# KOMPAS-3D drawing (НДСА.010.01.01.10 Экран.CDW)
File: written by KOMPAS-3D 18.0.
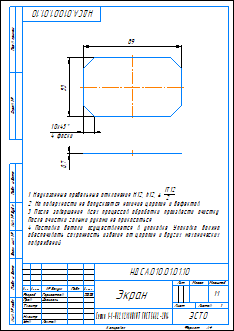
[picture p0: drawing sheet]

Sheet 1: A4, portrait

Document properties: Автор: Пользователь Windows; PDM_DOCXDTO: <item xmlns="http://appius.ru/pdm" xmlns:xs="http://www.w3.org/2001/XMLSchema" xmlns:xsi="http://www.w3.org/2001/XMLSchema-instance" xsi:type="item">  <element xmlns:d2p1="http://v8.1c.ru/8.1/data/enterprise/current-config" xsi:type="d2p1:CatalogRef.aps_Элемен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; Полное имя файла: F:\Temp\НДСА.010.01.01.10 Экран.CDW

Title block, sheet 1: Наименование: Экран; designation: НДСА.010.01.01.10; Материал: Сетка 1-1-032 12Х18Н10Т ГОСТ 5632-2014; scale: 1:1; sheets: 1; organisation: ЭСТО; Форматы листов документа: A4; stored path: E:\paul\Новая папка (5)\Виноградов\Новая папка\столик\Новая папка (9)\НДСА.010.01.00.00 СБ Корпус\НДСА.010.01.01.00 СБ Камера\НДСА.010.01.01.10 Экран.cdw; Разработал: Горностаев; Проверил: Дзензель; Утвердил: Локтев; Разработал, date: 27.03.2018

Views: Вид 1, Спереди, Проекционный вид 2
Referenced files in E:\paul\Новая папка (5)\Виноградов\Новая папка\столик\Новая папка (9)\НДСА.010.01.01.00 СБ Камера\: НДСА.010.01.01.10 Экран.m3d
Referenced files in E:\ICP\НДСА.010 Технологический модуль\НДСА.010.01 Корпус\НДСА.010.01.01 Камера\: НДСА.010.01.01.10 Экран.m3d
Dimensions and other numbers on the sheet: 89; 53; 10; 4 фаски; 0,7; 1:1; 1; 27.03.2018

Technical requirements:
  Неуказанные предельные отклонения H12, h12,    IT12 2 .
  На поверхности не допускается наличие царапин и дефектов.
  После завершения всех процессов обработки произвести очистку.
  После очистки голыми руками не прикасаться.
  Поставка детали осуществляется в упаковке. Упаковка должна
  обеспечивать сохранность изделия от царапин и других механических
  повреждений.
